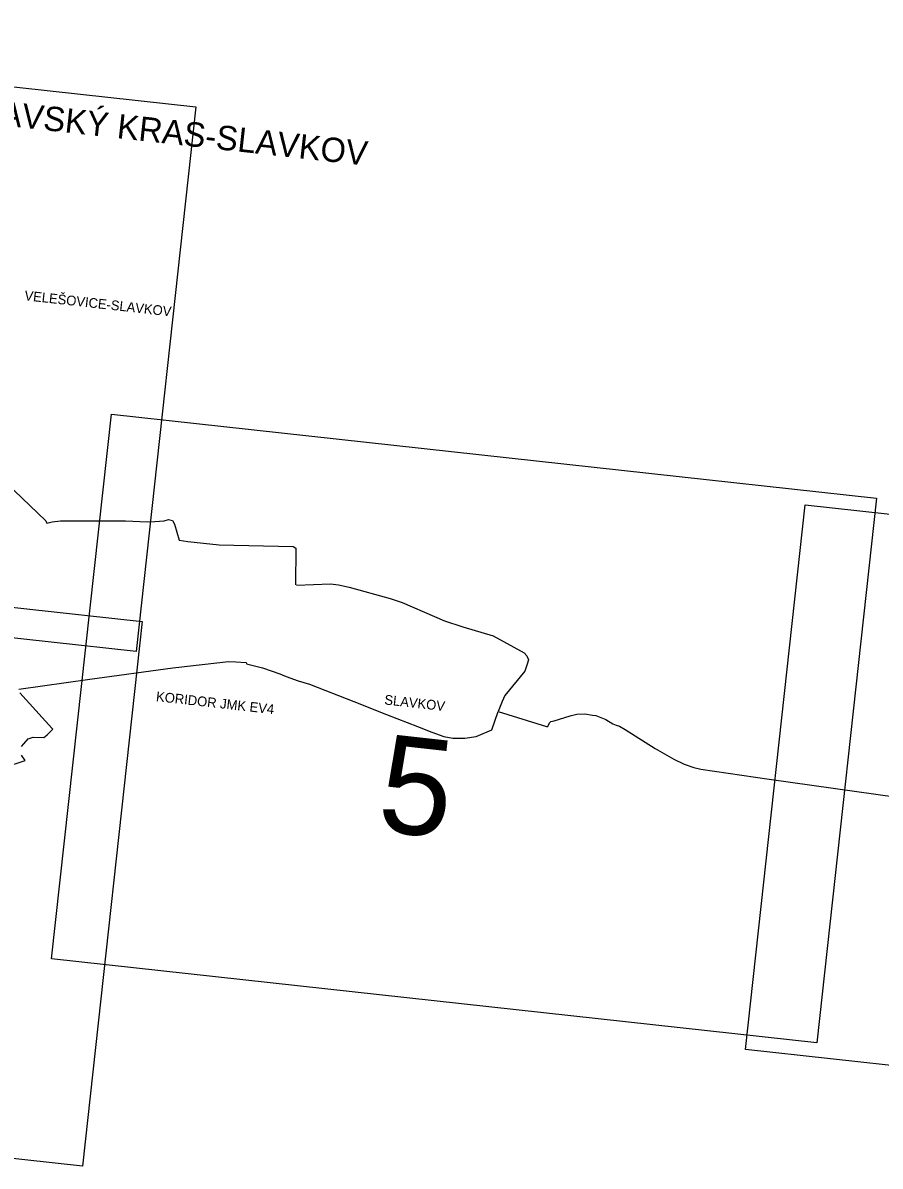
# Model space of a CAD drawing. Extents: x -678204 to -526855, y -1228851 to -1110393.
# Drawn here: x -580130 to -574848, y -1171102 to -1164054 of the extents above; entities that cross this region are included whole.
import ezdxf

# ---------------------------------------------------------------- set-up
doc = ezdxf.new("R2010")
doc.units = 0
for name, color, linetype in [('00_n_cyklo popisy detaily', 7, 'Continuous'), ('00_n_cyklo popisy ostatni', 7, 'Continuous'), ('00_n_cyklo provereni rekreacni hlavni', 7, 'Continuous'), ('00_n_cyklo provereni vedlejsi', 7, 'Continuous'), ('00_n_cyklo prujezdne rekreacni hlavni', 7, 'Continuous'), ('00_n_cyklo realizace rekreacni hlavni', 7, 'Continuous'), ('00_n_cyklo realizace rekreacni vedlejsi', 7, 'Continuous'), ('00_n_cyklo trasovani rekreacni hlavni', 7, 'Continuous'), ('00_n_cyklo trasovani rekreacni vedlejsi', 7, 'Continuous'), ('_HELP', 7, 'Continuous')]:
    doc.layers.add(name, color=color, linetype=linetype)

msp = doc.modelspace()

# ---------------------------------------------------------------- linework, layer by layer
at = {"layer": '00_n_cyklo provereni rekreacni hlavni'}
msp.add_line((-577239.9, -1168411.8), (-577200.7, -1168299.5), dxfattribs=at)
msp.add_lwpolyline([(-578363.7, -1168130.2), (-578091.4, -1168238.1), (-577889, -1168317.9), (-577698.3, -1168390.8), (-577610.9, -1168427.5), (-577535.9, -1168453.8), (-577480.6, -1168464.4), (-577406.1, -1168464.7), (-577337, -1168453.1), (-577239.9, -1168411.8)], dxfattribs=at)
at = {"layer": '00_n_cyklo provereni vedlejsi'}
for points in [[(-580919, -1166234.2), (-579989.5, -1167124.1), (-579982.8, -1167138.4), (-579949.1, -1167129.4), (-579898.3, -1167123.6), (-579497.8, -1167124.8), (-579364.8, -1167130.1), (-579317.1, -1167128), (-579260, -1167124.2), (-579233, -1167115.8)], [(-579233, -1167115.8), (-579207.7, -1167122.8), (-579196.2, -1167145.1), (-579167.2, -1167243), (-579114.3, -1167251.2), (-578920.3, -1167272.5), (-578465.5, -1167281.5), (-578448, -1167292.8), (-578450.7, -1167519.3)]]:
    msp.add_lwpolyline(points, dxfattribs=at)
at = {"layer": '00_n_cyklo prujezdne rekreacni hlavni'}
for points in [[(-580155.6, -1168161.8), (-579717.1, -1168101), (-579205.9, -1168031), (-579187.8, -1168028.9)], [(-579187.8, -1168028.9), (-578862.6, -1167992), (-578818, -1167992.7)], [(-578818, -1167992.7), (-578754.2, -1167996.7), (-578752.9, -1168005.7), (-578653, -1168030.6)], [(-578653, -1168030.6), (-578600.8, -1168049.2), (-578547.3, -1168067.8), (-578517.3, -1168079.3), (-578485, -1168092.2), (-578433.4, -1168109.3), (-578363.7, -1168130.2)], [(-580138.6, -1168514.2), (-580124.6, -1168499.2), (-580096.8, -1168467.7), (-580066.5, -1168457.3), (-580001.7, -1168460.4), (-579981.3, -1168443.1), (-579945.7, -1168408), (-579951, -1168402.3), (-580148, -1168184.7)], [(-576599.9, -1168325), (-576538.9, -1168348.6), (-576495.6, -1168376), (-576473.9, -1168384), (-576454.4, -1168390.7), (-576419.3, -1168410.3), (-576234.4, -1168526.7), (-576118.7, -1168593.6), (-576055.3, -1168623.1), (-575996.7, -1168644.3), (-575952.7, -1168654.8), (-575532.5, -1168715.6), (-574742.7, -1168826.9), (-574771, -1168908.2)], [(-580247.7, -1168644.6), (-580116.9, -1168600.6), (-580137.8, -1168569.4)]]:
    msp.add_lwpolyline(points, dxfattribs=at)
at = {"layer": '00_n_cyklo realizace rekreacni hlavni'}
msp.add_lwpolyline([(-577200.7, -1168299.5), (-576903.7, -1168391.1), (-576895.2, -1168391.7), (-576891.7, -1168383.2), (-576885.7, -1168368.7), (-576876.4, -1168361.3), (-576857.2, -1168357.8), (-576757.4, -1168325.1), (-576716.6, -1168316.6), (-576667.2, -1168313.6), (-576619.4, -1168321), (-576599.9, -1168325)], dxfattribs=at)
at = {"layer": '00_n_cyklo realizace rekreacni vedlejsi'}
msp.add_lwpolyline([(-578444.2, -1167519.6), (-578235.6, -1167512), (-578184.4, -1167518.7), (-578119.4, -1167533.8), (-577866.3, -1167603.4), (-577793.2, -1167627.2), (-577593.8, -1167713.5), (-577531.2, -1167739.6), (-577420.1, -1167776.6), (-577233.2, -1167833.3), (-577040.3, -1167938.1), (-577025.3, -1167955.5), (-577015.6, -1167980.3), (-577021.9, -1168006.7), (-577036.8, -1168050.3), (-577160.7, -1168201.6), (-577177.1, -1168237.1), (-577200.7, -1168299.5)], dxfattribs=at)
at = {"layer": '00_n_cyklo trasovani rekreacni hlavni'}
msp.add_line((-577239.9, -1168411.8), (-577200.7, -1168299.5), dxfattribs=at)
for points in [[(-580155.6, -1168161.8), (-579717.1, -1168101), (-579205.9, -1168031), (-579187.8, -1168028.9)], [(-579187.8, -1168028.9), (-578862.6, -1167992), (-578818, -1167992.7)], [(-578818, -1167992.7), (-578754.2, -1167996.7), (-578752.9, -1168005.7), (-578653, -1168030.6)], [(-578653, -1168030.6), (-578600.8, -1168049.2), (-578547.3, -1168067.8), (-578517.3, -1168079.3), (-578485, -1168092.2), (-578433.4, -1168109.3), (-578363.7, -1168130.2)], [(-578363.7, -1168130.2), (-578091.4, -1168238.1), (-577889, -1168317.9), (-577698.3, -1168390.8), (-577610.9, -1168427.5), (-577535.9, -1168453.8), (-577480.6, -1168464.4), (-577406.1, -1168464.7), (-577337, -1168453.1), (-577239.9, -1168411.8)], [(-580138.6, -1168514.2), (-580124.6, -1168499.2), (-580096.8, -1168467.7), (-580066.5, -1168457.3), (-580001.7, -1168460.4), (-579981.3, -1168443.1), (-579945.7, -1168408), (-579951, -1168402.3), (-580148, -1168184.7)], [(-577200.7, -1168299.5), (-576903.7, -1168391.1), (-576895.2, -1168391.7), (-576891.7, -1168383.2), (-576885.7, -1168368.7), (-576876.4, -1168361.3), (-576857.2, -1168357.8), (-576757.4, -1168325.1), (-576716.6, -1168316.6), (-576667.2, -1168313.6), (-576619.4, -1168321), (-576599.9, -1168325)], [(-576599.9, -1168325), (-576538.9, -1168348.6), (-576495.6, -1168376), (-576473.9, -1168384), (-576454.4, -1168390.7), (-576419.3, -1168410.3), (-576234.4, -1168526.7), (-576118.7, -1168593.6), (-576055.3, -1168623.1), (-575996.7, -1168644.3), (-575952.7, -1168654.8), (-575532.5, -1168715.6), (-574742.7, -1168826.9), (-574771, -1168908.2)], [(-580247.7, -1168644.6), (-580116.9, -1168600.6), (-580137.8, -1168569.4)]]:
    msp.add_lwpolyline(points, dxfattribs=at)
at = {"layer": '00_n_cyklo trasovani rekreacni vedlejsi'}
for points in [[(-580919, -1166234.2), (-579989.5, -1167124.1), (-579982.8, -1167138.4), (-579949.1, -1167129.4), (-579898.3, -1167123.6), (-579497.8, -1167124.8), (-579364.8, -1167130.1), (-579317.1, -1167128), (-579260, -1167124.2), (-579233, -1167115.8)], [(-579233, -1167115.8), (-579207.7, -1167122.8), (-579196.2, -1167145.1), (-579167.2, -1167243), (-579114.3, -1167251.2), (-578920.3, -1167272.5), (-578465.5, -1167281.5), (-578448, -1167292.8), (-578450.7, -1167519.3)], [(-578444.2, -1167519.6), (-578235.6, -1167512), (-578184.4, -1167518.7), (-578119.4, -1167533.8), (-577866.3, -1167603.4), (-577793.2, -1167627.2), (-577593.8, -1167713.5), (-577531.2, -1167739.6), (-577420.1, -1167776.6), (-577233.2, -1167833.3), (-577040.3, -1167938.1), (-577025.3, -1167955.5), (-577015.6, -1167980.3), (-577021.9, -1168006.7), (-577036.8, -1168050.3), (-577160.7, -1168201.6), (-577177.1, -1168237.1), (-577200.7, -1168299.5)]]:
    msp.add_lwpolyline(points, dxfattribs=at)
at = {"layer": '_HELP'}
for points in [[(-583778.8, -1164054.2), (-579064.3, -1164571.9), (-579433, -1167929.4), (-584147.5, -1167411.7)], [(-579584.4, -1166467.1), (-574869.9, -1166984.8), (-575238.5, -1170342.3), (-579953.1, -1169824.6)], [(-575309.6, -1167024.7), (-570595.1, -1167542.4), (-570963.7, -1170899.9), (-575678.3, -1170382.2)], [(-584109.1, -1167226.8), (-579394.6, -1167744.5), (-579763.3, -1171102), (-584477.8, -1170584.3)]]:
    msp.add_lwpolyline(points, close=True, dxfattribs=at)

# ---------------------------------------------------------------- texts
at = {"layer": '00_n_cyklo popisy detaily'}
for s, p in [('VELEŠOVICE-SLAVKOV', (-580122.6, -1165763.8)), ('KORIDOR JMK EV4', (-579311.8, -1168235.4)), ('SLAVKOV', (-577905, -1168255.4))]:
    msp.add_text(s, height=60, rotation=353.68355, dxfattribs=at).set_placement(p)
at = {"layer": '00_n_cyklo popisy ostatni'}
msp.add_text('MORAVSKÝ KRAS-SLAVKOV', height=150, rotation=353.68355, dxfattribs=at).set_placement((-580740.5, -1164632.9))
at = {"layer": '_HELP'}
msp.add_text('5', height=600, rotation=353.68355, dxfattribs=at).set_placement((-577957.1, -1169032.7))

doc.saveas('drawing.dxf')
